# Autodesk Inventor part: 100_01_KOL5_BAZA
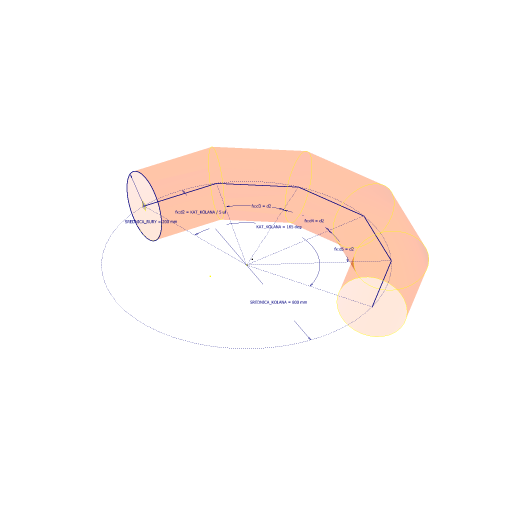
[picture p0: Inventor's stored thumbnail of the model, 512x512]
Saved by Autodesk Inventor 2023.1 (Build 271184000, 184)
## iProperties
Created: 2017-01
Part Number: 100_01_KOL5_BAZA
Material: Stal
Document SubType Name: Modeling
Designer: F.Stasiak
Density: 7.85 g/cm^3
Appearance: Stal
Catalog Web Link: www.expertbooks.pl
Manager: www.cadconsulting.pl
Company: Fabian Stasiak CAD Consulting
Author: F.Stasiak
Subject: Zbiór ćwiczeń. Autodesk Inventor 2020. Kurs zaawansowany
## Parameters: ELBO_ANGLE = 165 deg, d2 = 33 deg, d3 = 33 deg, d4 = 33 deg, d5 = 33 deg, d7 = 0, d8 = 0
